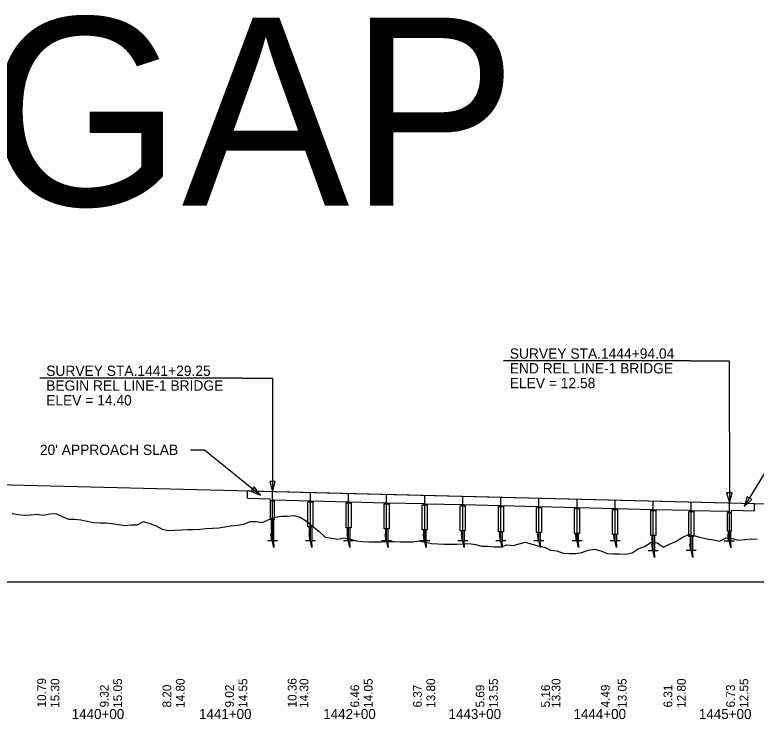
# Model space of a CAD drawing. Extents: x 2360994 to 2383826, y 330623 to 403123.
# Drawn here: x 2369149 to 2369741, y 376763 to 377325 of the extents above; entities that cross this region are included whole.
import ezdxf

# ---------------------------------------------------------------- set-up
doc = ezdxf.new("R2010")
doc.units = 0
for name, color, linetype in [('BR_CENTER LINES', 7, 'Continuous'), ('BR_CONCRETE', 7, 'Continuous'), ('BR_DETAILS', 7, 'Continuous'), ('RD_DDB_Profile_EX', 7, 'Continuous'), ('RD_DDB_Profile_PR', 7, 'Continuous'), ('RD_DDB_StaTX', 7, 'Continuous'), ('RD_DDB_StripGrade', 7, 'Continuous'), ('RD_GPK_Profile_Cell', 7, 'Continuous'), ('RD_TX_Profile', 7, 'Continuous')]:
    doc.layers.add(name, color=color, linetype=linetype)

msp = doc.modelspace()

# ---------------------------------------------------------------- linework, layer by layer
at = {"layer": 'BR_CENTER LINES'}
for p, q in [((2369354.82, 376905.51), (2369354.82, 376944.89)), ((2369385.22, 376905.51), (2369385.22, 376944.13)), ((2369415.62, 376905.51), (2369415.62, 376943.37)), ((2369446.01, 376905.51), (2369446.01, 376942.61)), ((2369476.41, 376905.51), (2369476.41, 376941.85)), ((2369506.81, 376905.51), (2369506.81, 376941.09)), ((2369537.21, 376905.51), (2369537.21, 376940.33)), ((2369567.61, 376905.51), (2369567.61, 376939.57)), ((2369598.01, 376905.51), (2369598.01, 376938.81)), ((2369628.41, 376905.51), (2369628.41, 376938.05)), ((2369658.81, 376897.48), (2369658.81, 376937.29)), ((2369689.21, 376897.71), (2369689.21, 376936.53)), ((2369719.61, 376905.19), (2369719.61, 376935.77))]:
    msp.add_line(p, q, dxfattribs=at)
at = {"layer": 'BR_CONCRETE'}
for p, q in [((2369334.82, 376945.39), (2369739.61, 376935.27)), ((2369334.82, 376939.56), (2369334.82, 376945.39)), ((2369354.82, 376937.39), (2369354.82, 376944.89)), ((2369334.82, 376939.56), (2369352.97, 376939.11)), ((2369353.32, 376937.39), (2369352.97, 376939.11)), ((2369355.82, 376937.89), (2369355.88, 376938.2)), ((2369355.82, 376937.39), (2369355.82, 376937.89)), ((2369355.88, 376938.2), (2369384.4, 376937.49)), ((2369384.47, 376937.17), (2369384.4, 376937.49)), ((2369384.47, 376936.63), (2369384.47, 376937.17)), ((2369385.97, 376937.14), (2369386.03, 376937.45)), ((2369385.97, 376936.63), (2369385.97, 376937.14)), ((2369386.03, 376937.45), (2369414.8, 376936.73)), ((2369414.87, 376936.41), (2369414.8, 376936.73)), ((2369414.87, 376935.87), (2369414.87, 376936.41)), ((2369416.37, 376936.38), (2369416.43, 376936.69)), ((2369416.37, 376935.87), (2369416.37, 376936.38)), ((2369416.43, 376936.69), (2369445.2, 376935.97)), ((2369445.26, 376935.65), (2369445.2, 376935.97)), ((2369445.26, 376935.11), (2369445.26, 376935.65)), ((2369446.76, 376935.62), (2369446.83, 376935.93)), ((2369446.76, 376935.11), (2369446.76, 376935.62)), ((2369446.83, 376935.93), (2369475.6, 376935.21)), ((2369719.61, 376928.27), (2369719.61, 376935.77)), ((2369475.66, 376934.89), (2369475.6, 376935.21)), ((2369475.66, 376934.35), (2369475.66, 376934.89)), ((2369477.16, 376934.86), (2369477.23, 376935.17)), ((2369477.16, 376934.35), (2369477.16, 376934.86)), ((2369477.23, 376935.17), (2369506, 376934.45)), ((2369506.06, 376934.13), (2369506, 376934.45)), ((2369506.06, 376933.59), (2369506.06, 376934.13)), ((2369507.56, 376934.1), (2369507.63, 376934.41)), ((2369507.56, 376933.59), (2369507.56, 376934.1)), ((2369507.63, 376934.41), (2369536.4, 376933.69)), ((2369536.46, 376933.37), (2369536.4, 376933.69)), ((2369536.46, 376932.83), (2369536.46, 376933.37)), ((2369537.96, 376933.34), (2369538.02, 376933.65)), ((2369537.96, 376932.83), (2369537.96, 376933.34)), ((2369538.02, 376933.65), (2369566.8, 376932.93)), ((2369566.86, 376932.61), (2369566.8, 376932.93)), ((2369566.86, 376932.07), (2369566.86, 376932.61)), ((2369568.36, 376932.58), (2369568.42, 376932.89)), ((2369568.36, 376932.07), (2369568.36, 376932.58)), ((2369568.42, 376932.89), (2369597.2, 376932.17)), ((2369597.26, 376931.85), (2369597.2, 376932.17)), ((2369597.26, 376931.31), (2369597.26, 376931.85)), ((2369598.76, 376931.82), (2369598.82, 376932.13)), ((2369598.76, 376931.31), (2369598.76, 376931.82)), ((2369598.82, 376932.13), (2369627.6, 376931.41)), ((2369627.66, 376931.09), (2369627.6, 376931.41)), ((2369627.66, 376930.55), (2369627.66, 376931.09)), ((2369629.16, 376931.06), (2369629.22, 376931.37)), ((2369629.16, 376930.55), (2369629.16, 376931.06)), ((2369629.22, 376931.37), (2369658, 376930.65)), ((2369658.06, 376930.33), (2369658, 376930.65)), ((2369658.06, 376929.79), (2369658.06, 376930.33)), ((2369659.56, 376930.3), (2369659.62, 376930.61)), ((2369659.56, 376929.79), (2369659.56, 376930.3)), ((2369659.62, 376930.61), (2369688.4, 376929.89)), ((2369688.46, 376929.57), (2369688.4, 376929.89)), ((2369688.46, 376929.03), (2369688.46, 376929.57)), ((2369689.96, 376929.54), (2369690.02, 376929.85)), ((2369689.96, 376929.03), (2369689.96, 376929.54)), ((2369690.02, 376929.85), (2369718.55, 376929.13)), ((2369721.11, 376927.91), (2369721.5, 376929.89)), ((2369721.5, 376929.89), (2369739.61, 376929.44)), ((2369739.61, 376929.44), (2369739.61, 376935.27)), ((2369718.61, 376928.82), (2369718.55, 376929.13)), ((2369718.61, 376928.27), (2369718.61, 376928.82)), ((2369353.82, 376922.39), (2369353.82, 376910.17)), ((2369355.82, 376922.39), (2369355.82, 376905.54)), ((2369384.22, 376916.63), (2369384.22, 376910.17)), ((2369386.22, 376916.63), (2369386.22, 376905.54)), ((2369414.62, 376915.87), (2369414.62, 376910.17)), ((2369416.62, 376915.87), (2369416.62, 376905.54)), ((2369445.01, 376915.11), (2369445.01, 376910.17)), ((2369447.01, 376915.11), (2369447.01, 376905.54)), ((2369475.41, 376914.35), (2369475.41, 376910.17)), ((2369477.41, 376914.35), (2369477.41, 376905.54)), ((2369505.81, 376913.59), (2369505.81, 376910.17)), ((2369507.81, 376913.59), (2369507.81, 376905.54)), ((2369536.21, 376912.83), (2369536.21, 376910.17)), ((2369538.21, 376912.83), (2369538.21, 376905.54)), ((2369566.61, 376912.07), (2369566.61, 376910.17)), ((2369568.61, 376912.07), (2369568.61, 376905.54)), ((2369718.61, 376913.27), (2369718.61, 376909.85)), ((2369720.61, 376913.27), (2369720.61, 376905.22)), ((2369597.01, 376911.31), (2369597.01, 376910.17)), ((2369599.01, 376911.31), (2369599.01, 376905.54)), ((2369627.41, 376910.55), (2369627.41, 376910.17)), ((2369629.41, 376910.55), (2369629.41, 376905.54)), ((2369657.81, 376909.79), (2369657.81, 376902.14)), ((2369659.81, 376909.79), (2369659.81, 376897.51)), ((2369688.21, 376909.03), (2369688.21, 376902.37)), ((2369690.21, 376909.03), (2369690.21, 376897.74))]:
    msp.add_line(p, q, dxfattribs=at)
for points in [[(2369353.32, 376922.39), (2369353.32, 376937.39), (2369356.32, 376937.39), (2369356.32, 376922.39)], [(2369383.22, 376936.63), (2369387.22, 376936.63), (2369387.22, 376916.63), (2369383.22, 376916.63)], [(2369413.62, 376935.87), (2369417.62, 376935.87), (2369417.62, 376915.87), (2369413.62, 376915.87)], [(2369444.01, 376935.11), (2369448.01, 376935.11), (2369448.01, 376915.11), (2369444.01, 376915.11)], [(2369474.41, 376934.35), (2369478.41, 376934.35), (2369478.41, 376914.35), (2369474.41, 376914.35)], [(2369504.81, 376933.59), (2369508.81, 376933.59), (2369508.81, 376913.59), (2369504.81, 376913.59)], [(2369535.21, 376932.83), (2369539.21, 376932.83), (2369539.21, 376912.83), (2369535.21, 376912.83)], [(2369565.61, 376932.07), (2369569.61, 376932.07), (2369569.61, 376912.07), (2369565.61, 376912.07)], [(2369596.01, 376931.31), (2369600.01, 376931.31), (2369600.01, 376911.31), (2369596.01, 376911.31)], [(2369626.41, 376930.55), (2369630.41, 376930.55), (2369630.41, 376910.55), (2369626.41, 376910.55)], [(2369656.81, 376929.79), (2369660.81, 376929.79), (2369660.81, 376909.79), (2369656.81, 376909.79)], [(2369687.21, 376929.03), (2369691.21, 376929.03), (2369691.21, 376909.03), (2369687.21, 376909.03)], [(2369718.11, 376913.27), (2369718.11, 376928.27), (2369721.11, 376928.27), (2369721.11, 376913.27)]]:
    msp.add_lwpolyline(points, close=True, dxfattribs=at)
at = {"layer": 'BR_DETAILS'}
for p, q in [((2369355.97, 376900.15), (2369353.67, 376910.87)), ((2369353.67, 376910.87), (2369353.99, 376905.54)), ((2369386.37, 376900.15), (2369384.07, 376910.87)), ((2369384.07, 376910.87), (2369384.39, 376905.54)), ((2369416.77, 376900.15), (2369414.46, 376910.87)), ((2369414.46, 376910.87), (2369414.79, 376905.54)), ((2369447.17, 376900.15), (2369444.86, 376910.87)), ((2369444.86, 376910.87), (2369445.19, 376905.54)), ((2369477.57, 376900.15), (2369475.26, 376910.87)), ((2369475.26, 376910.87), (2369475.59, 376905.54)), ((2369507.96, 376900.15), (2369505.66, 376910.87)), ((2369505.66, 376910.87), (2369505.99, 376905.54)), ((2369538.36, 376900.15), (2369536.06, 376910.87)), ((2369536.06, 376910.87), (2369536.39, 376905.54)), ((2369568.76, 376900.15), (2369566.46, 376910.87)), ((2369566.46, 376910.87), (2369566.79, 376905.54)), ((2369599.16, 376900.15), (2369596.86, 376910.87)), ((2369596.86, 376910.87), (2369597.18, 376905.54)), ((2369629.56, 376900.15), (2369627.26, 376910.87)), ((2369627.26, 376910.87), (2369627.58, 376905.54)), ((2369720.76, 376899.83), (2369718.46, 376910.56)), ((2369718.46, 376910.56), (2369718.78, 376905.22)), ((2369353.99, 376905.54), (2369350.82, 376905.54)), ((2369358.82, 376905.54), (2369355.64, 376905.54)), ((2369355.64, 376905.54), (2369355.97, 376900.15)), ((2369384.39, 376905.54), (2369381.22, 376905.54)), ((2369389.22, 376905.54), (2369386.04, 376905.54)), ((2369386.04, 376905.54), (2369386.37, 376900.15)), ((2369414.79, 376905.54), (2369411.62, 376905.54)), ((2369419.62, 376905.54), (2369416.44, 376905.54)), ((2369416.44, 376905.54), (2369416.77, 376900.15)), ((2369445.19, 376905.54), (2369442.01, 376905.54)), ((2369450.01, 376905.54), (2369446.84, 376905.54)), ((2369446.84, 376905.54), (2369447.17, 376900.15)), ((2369475.59, 376905.54), (2369472.41, 376905.54)), ((2369480.41, 376905.54), (2369477.24, 376905.54)), ((2369477.24, 376905.54), (2369477.57, 376900.15)), ((2369505.99, 376905.54), (2369502.81, 376905.54)), ((2369510.81, 376905.54), (2369507.64, 376905.54)), ((2369507.64, 376905.54), (2369507.96, 376900.15)), ((2369536.39, 376905.54), (2369533.21, 376905.54)), ((2369541.21, 376905.54), (2369538.04, 376905.54)), ((2369538.04, 376905.54), (2369538.36, 376900.15)), ((2369566.79, 376905.54), (2369563.61, 376905.54)), ((2369571.61, 376905.54), (2369568.44, 376905.54)), ((2369568.44, 376905.54), (2369568.76, 376900.15)), ((2369597.18, 376905.54), (2369594.01, 376905.54)), ((2369602.01, 376905.54), (2369598.84, 376905.54)), ((2369598.84, 376905.54), (2369599.16, 376900.15)), ((2369627.58, 376905.54), (2369624.41, 376905.54)), ((2369632.41, 376905.54), (2369629.23, 376905.54)), ((2369629.23, 376905.54), (2369629.56, 376900.15)), ((2369659.96, 376892.12), (2369657.66, 376902.85)), ((2369657.66, 376902.85), (2369657.98, 376897.51)), ((2369690.36, 376892.35), (2369688.06, 376903.08)), ((2369688.06, 376903.08), (2369688.38, 376897.74)), ((2369718.78, 376905.22), (2369715.61, 376905.22)), ((2369723.61, 376905.22), (2369720.43, 376905.22)), ((2369720.43, 376905.22), (2369720.76, 376899.83)), ((2369657.98, 376897.51), (2369654.81, 376897.51)), ((2369662.81, 376897.51), (2369659.63, 376897.51)), ((2369659.63, 376897.51), (2369659.96, 376892.12)), ((2369688.38, 376897.74), (2369685.21, 376897.74)), ((2369693.21, 376897.74), (2369690.03, 376897.74)), ((2369690.03, 376897.74), (2369690.36, 376892.35))]:
    msp.add_line(p, q, dxfattribs=at)
at = {"layer": 'RD_DDB_Profile_EX'}
for points in [[(2369146.95, 376927.24), (2369151.95, 376926.55), (2369156.95, 376926.05), (2369161.95, 376926.27), (2369166.95, 376926.93), (2369171.95, 376925.96), (2369176.95, 376927.18), (2369181.95, 376927.33), (2369186.95, 376925.08), (2369191.95, 376922.83), (2369196.95, 376922.85), (2369201.95, 376922.4), (2369206.95, 376921.21), (2369211.95, 376920.21), (2369216.95, 376920), (2369221.95, 376919.86), (2369226.95, 376919.37), (2369231.95, 376918.64), (2369236.95, 376917.88), (2369241.95, 376918.28), (2369246.95, 376918.35), (2369251.95, 376920.98), (2369256.95, 376919.34), (2369261.95, 376917.55), (2369266.95, 376914.93), (2369271.95, 376913.76), (2369276.95, 376913.94), (2369281.95, 376914.32), (2369286.95, 376914.52), (2369291.95, 376914.67), (2369296.95, 376914.93), (2369301.95, 376915.5), (2369306.95, 376915.73), (2369311.95, 376915.86), (2369316.95, 376916.72), (2369321.95, 376917.56), (2369326.95, 376918.15)], [(2369326.95, 376918.15), (2369331.95, 376918.85), (2369336.95, 376920.96), (2369341.95, 376920.9), (2369346.95, 376920.15), (2369351.95, 376922.49), (2369356.95, 376924.49), (2369361.95, 376925.33), (2369366.95, 376925.16), (2369371.95, 376925.71), (2369376.95, 376924.3), (2369381.95, 376921.28), (2369386.95, 376917.37), (2369391.95, 376913.12), (2369396.95, 376908.39), (2369401.95, 376907.57), (2369406.95, 376906.96), (2369411.95, 376907.82), (2369416.95, 376906.9), (2369421.95, 376905.43), (2369426.95, 376905.12), (2369431.95, 376904.81), (2369436.95, 376904.62), (2369441.95, 376904.66), (2369446.95, 376904.89), (2369451.95, 376905.05), (2369456.95, 376904.69), (2369461.95, 376904.65), (2369466.95, 376904.73), (2369471.95, 376905.48), (2369476.95, 376904.42), (2369481.95, 376903.5), (2369486.95, 376903.25), (2369491.95, 376903), (2369496.95, 376902.96), (2369501.95, 376902.94), (2369506.95, 376903.26), (2369511.95, 376903.35), (2369516.95, 376902.58), (2369521.95, 376901.4), (2369526.95, 376901.3), (2369531.95, 376900.73), (2369536.95, 376900.79), (2369541.95, 376902.33), (2369546.95, 376901.81), (2369551.95, 376903.08), (2369556.95, 376904.59), (2369561.95, 376902.98), (2369566.95, 376901.48), (2369571.95, 376900.38), (2369576.95, 376898.02), (2369581.95, 376897.52), (2369586.95, 376895.6), (2369591.95, 376895.4), (2369596.95, 376895.46), (2369601.95, 376896.27), (2369606.95, 376898.09), (2369611.95, 376899), (2369616.95, 376897.51), (2369621.95, 376895.46), (2369626.95, 376895.3), (2369631.95, 376895.11), (2369636.95, 376895.02), (2369641.95, 376896.08), (2369646.95, 376899.21), (2369651.95, 376901.14), (2369656.95, 376904.16), (2369661.95, 376904.01), (2369666.95, 376900.5), (2369671.95, 376902.91), (2369676.95, 376905.01), (2369681.95, 376908.21), (2369686.95, 376910.56), (2369691.95, 376909.65), (2369696.95, 376908.25), (2369701.95, 376907.03), (2369706.95, 376906.34), (2369711.95, 376905.21), (2369716.95, 376907.91), (2369721.95, 376907.39), (2369726.95, 376906.19), (2369731.95, 376906.49), (2369736.95, 376907.13), (2369741.95, 376906.91)]]:
    msp.add_lwpolyline(points, dxfattribs=at)
at = {"layer": 'RD_DDB_Profile_PR'}
msp.add_line((2368940.57, 376955.25), (2369750.57, 376935), dxfattribs=at)
at = {"layer": 'RD_GPK_Profile_Cell'}
msp.add_line((2368825.57, 376872.88), (2370425.57, 376872.88), dxfattribs=at)
at = {"layer": 'RD_TX_Profile'}
for p, q in [((2369688.46, 377049.06), (2369539.33, 377049.06)), ((2369330.48, 377035.31), (2369169.25, 377035.31))]:
    msp.add_line(p, q, dxfattribs=at)
for points in [[(2369688.46, 377049.06), (2369719.54, 377049.06), (2369719.61, 376935.77)], [(2369330.48, 377035.31), (2369354.85, 377035.31), (2369354.82, 376944.89)], [(2369289.34, 376978.15), (2369300.71, 376978.15), (2369345.22, 376941.87)], [(2369767.04, 376970.37), (2369754.42, 376970.37), (2369731.52, 376932.84)]]:
    msp.add_lwpolyline(points, dxfattribs=at)
for points in [[(2369337.71, 376945.24), (2369345.22, 376941.87), (2369340.4, 376948.55)], [(2369352.69, 376952.85), (2369354.82, 376944.89), (2369356.95, 376952.85)], [(2369717.47, 376943.73), (2369719.61, 376935.77), (2369721.74, 376943.73)], [(2369733.84, 376940.74), (2369731.52, 376932.84), (2369737.48, 376938.52)]]:
    msp.add_lwpolyline(points, close=True, dxfattribs=at)

# ---------------------------------------------------------------- texts
at = {"layer": 'RD_DDB_StaTX'}
for s, p in [('1440+00', (2369194.59, 376763.4)), ('1441+00', (2369296.21, 376763.4)), ('1442+00', (2369395.41, 376763.4)), ('1443+00', (2369495.44, 376763.4)), ('1444+00', (2369595.19, 376763.4)), ('1445+00', (2369695.33, 376763.4))]:
    msp.add_text(s, height=8, dxfattribs=at).set_placement(p)
at = {"layer": 'RD_DDB_StripGrade'}
for s, p in [('10.79', (2369174.1, 376772.63)), ('15.30', (2369184.77, 376772.33)), ('15.05', (2369234.77, 376772.33)), ('14.80', (2369284.77, 376772.33)), ('14.55', (2369334.77, 376772.33)), ('10.36', (2369374.1, 376772.63)), ('14.30', (2369383.53, 376772.33)), ('14.05', (2369434.77, 376772.33)), ('13.80', (2369484.77, 376772.33)), ('13.55', (2369534.77, 376772.33)), ('13.30', (2369584.77, 376772.33)), ('13.05', (2369637.58, 376772.33)), ('12.80', (2369684.77, 376772.33)), ('12.55', (2369734.77, 376772.33)), ('9.32', (2369224.1, 376772.63)), ('8.20', (2369274.1, 376772.63)), ('9.02', (2369324.1, 376772.63)), ('6.46', (2369424.1, 376772.63)), ('6.37', (2369474.1, 376772.63)), ('5.69', (2369524.1, 376772.63)), ('5.16', (2369576.4, 376772.63)), ('4.49', (2369624.1, 376772.63)), ('6.31', (2369674.1, 376772.63)), ('6.73', (2369724.1, 376772.63))]:
    msp.add_text(s, height=7, rotation=90, dxfattribs=at).set_placement(p)
at = {"layer": 'RD_GPK_Profile_Cell'}
msp.add_text('NOGAP', height=150, dxfattribs=at).set_placement((2368825.57, 377172.88))
at = {"layer": 'RD_TX_Profile'}
for s, p in [('SURVEY STA.1444+94.04', (2369544.33, 377050.83)), ('SURVEY STA.1441+29.25', (2369174.25, 377037.08)), ('END REL LINE-1 BRIDGE', (2369544.33, 377039.06)), ('BEGIN REL LINE-1 BRIDGE', (2369174.25, 377025.31)), ('ELEV = 12.58', (2369544.33, 377027.3)), ('ELEV = 14.40', (2369174.25, 377013.55)), ("20' APPROACH SLAB", (2369169.21, 376974.04))]:
    msp.add_text(s, height=8.2353, dxfattribs=at).set_placement(p)

doc.saveas('drawing.dxf')
